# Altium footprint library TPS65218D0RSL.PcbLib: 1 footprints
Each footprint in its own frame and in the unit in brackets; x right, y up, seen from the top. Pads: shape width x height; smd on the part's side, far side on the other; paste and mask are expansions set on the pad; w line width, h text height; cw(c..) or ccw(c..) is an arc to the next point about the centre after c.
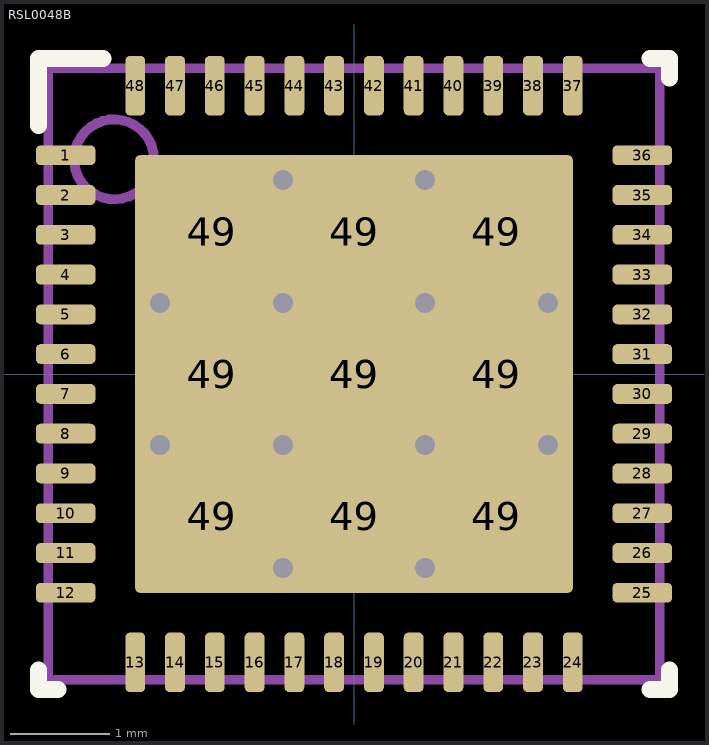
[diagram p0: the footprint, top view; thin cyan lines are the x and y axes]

## RSL0048B [mm]
height 1
pads (58):
  rrect50% 0.6x0.2 smd: 1(-2.9,2.2) 2(-2.9,1.8) 3(-2.9,1.4) 4(-2.9,1) 5(-2.9,0.6) 6(-2.9,0.2) 7(-2.9,-0.2) 8(-2.9,-0.6) 9(-2.9,-1) 10(-2.9,-1.4) 11(-2.9,-1.8) 12(-2.9,-2.2) 25(2.9,-2.2) 26(2.9,-1.8) 27(2.9,-1.4) 28(2.9,-1) 29(2.9,-0.6) 30(2.9,-0.2) 31(2.9,0.2) 32(2.9,0.6) 33(2.9,1) 34(2.9,1.4) 35(2.9,1.8) 36(2.9,2.2)
  rrect50% 0.2x0.6 smd: 13(-2.2,-2.9) 14(-1.8,-2.9) 15(-1.4,-2.9) 16(-1,-2.9) 17(-0.6,-2.9) 18(-0.2,-2.9) 19(0.2,-2.9) 20(0.6,-2.9) 21(1,-2.9) 22(1.4,-2.9) 23(1.8,-2.9) 24(2.2,-2.9) 37(2.2,2.9) 38(1.8,2.9) 39(1.4,2.9) 40(1,2.9) 41(0.6,2.9) 42(0.2,2.9) 43(-0.2,2.9) 44(-0.6,2.9) 45(-1,2.9) 46(-1.4,2.9) 47(-1.8,2.9) 48(-2.2,2.9)
  rrect50% 1.23x1.23 on Top Paste: 49(-1.43,-1.43) 49(-1.43,0) 49(-1.43,1.43) 49(0,-1.43) 49(0,0) 49(0,1.43) 49(1.43,-1.43) 49(1.43,0) 49(1.43,1.43)
  rrect2% 4.4x4.4 smd paste-2.2: 49(0,0)
via 0.715,0.715 diameter 0.5 hole 0.2
via 1.95,0.715 diameter 0.5 hole 0.2
via 0.715,1.95 diameter 0.5 hole 0.2
via -0.715,1.95 diameter 0.5 hole 0.2
via -0.715,-1.95 diameter 0.5 hole 0.2
via 0.715,-1.95 diameter 0.5 hole 0.2
via -1.95,0.715 diameter 0.5 hole 0.2
via -0.715,0.715 diameter 0.5 hole 0.2
via -0.715,-0.715 diameter 0.5 hole 0.2
via -1.95,-0.715 diameter 0.5 hole 0.2
via 1.95,-0.715 diameter 0.5 hole 0.2
via 0.715,-0.715 diameter 0.5 hole 0.2
Top Overlay:
  lines w0.17: -3.175,-2.975 -3.175,-3.175 -2.975,-3.175 ; -3.175,2.5 -3.175,3.175 -2.525,3.175 ; 2.975,-3.175 3.175,-3.175 3.175,-2.975 ; 2.975,3.175 3.175,3.175 3.175,2.975
Mechanical 5:
  circle w0.1: c-2.413,2.159 r0.402
  lines w0.1: -3.075,-3.075 3.075,-3.075 3.075,3.075 -3.075,3.075 -3.075,-3.075 ; -3.075,-2.33 -3.075,-2.07 -3.075,-2.33 ; -3.075,-1.93 -3.075,-1.67 -3.075,-1.93 ; -3.075,-1.53 -3.075,-1.27 -3.075,-1.53 ; -3.075,-1.13 -3.075,-0.87 -3.075,-1.13 ; -3.075,-0.73 -3.075,-0.47 -3.075,-0.73 ; -3.075,-0.33 -3.075,-0.07 -3.075,-0.33 ; -3.075,0.07 -3.075,0.33 -3.075,0.07 ; -3.075,0.47 -3.075,0.73 -3.075,0.47 ; -3.075,0.87 -3.075,1.13 -3.075,0.87 ; -3.075,1.27 -3.075,1.53 -3.075,1.27 ; -3.075,1.67 -3.075,1.93 -3.075,1.67 ; -3.075,2.07 -3.075,2.33 -3.075,2.07 ; -2.33,-3.075 -2.07,-3.075 -2.33,-3.075 ; -2.33,3.075 -2.07,3.075 -2.33,3.075 ; -1.93,-3.075 -1.67,-3.075 -1.93,-3.075 ; -1.93,3.075 -1.67,3.075 -1.93,3.075 ; -1.53,-3.075 -1.27,-3.075 -1.53,-3.075 ; -1.53,3.075 -1.27,3.075 -1.53,3.075 ; -1.13,-3.075 -0.87,-3.075 -1.13,-3.075 ; -1.13,3.075 -0.87,3.075 -1.13,3.075 ; -0.73,-3.075 -0.47,-3.075 -0.73,-3.075 ; -0.73,3.075 -0.47,3.075 -0.73,3.075 ; -0.33,-3.075 -0.07,-3.075 -0.33,-3.075 ; -0.33,3.075 -0.07,3.075 -0.33,3.075 ; 0.07,-3.075 0.33,-3.075 0.07,-3.075 ; 0.07,3.075 0.33,3.075 0.07,3.075 ; 0.47,-3.075 0.73,-3.075 0.47,-3.075 ; 0.47,3.075 0.73,3.075 0.47,3.075 ; 0.87,-3.075 1.13,-3.075 0.87,-3.075 ; 0.87,3.075 1.13,3.075 0.87,3.075 ; 1.27,-3.075 1.53,-3.075 1.27,-3.075 ; 1.27,3.075 1.53,3.075 1.27,3.075 ; 1.67,-3.075 1.93,-3.075 1.67,-3.075 ; 1.67,3.075 1.93,3.075 1.67,3.075 ; 2.07,-3.075 2.33,-3.075 2.07,-3.075 ; 2.07,3.075 2.33,3.075 2.07,3.075 ; 3.075,-2.33 3.075,-2.07 3.075,-2.33 ; 3.075,-1.93 3.075,-1.67 3.075,-1.93 ; 3.075,-1.53 3.075,-1.27 3.075,-1.53 ; 3.075,-1.13 3.075,-0.87 3.075,-1.13 ; 3.075,-0.73 3.075,-0.47 3.075,-0.73 ; 3.075,-0.33 3.075,-0.07 3.075,-0.33 ; 3.075,0.07 3.075,0.33 3.075,0.07 ; 3.075,0.47 3.075,0.73 3.075,0.47 ; 3.075,0.87 3.075,1.13 3.075,0.87 ; 3.075,1.27 3.075,1.53 3.075,1.27 ; 3.075,1.67 3.075,1.93 3.075,1.67 ; 3.075,2.07 3.075,2.33 3.075,2.07
  text ".Designator" at -1.905,-0.508 h1.02
3D body: height 1.01, standoff 0, extent -2.814,1.758 -2.012,2.56
3D body: height 1, standoff 0, extent -3.074,-3.074 3.074,3.074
